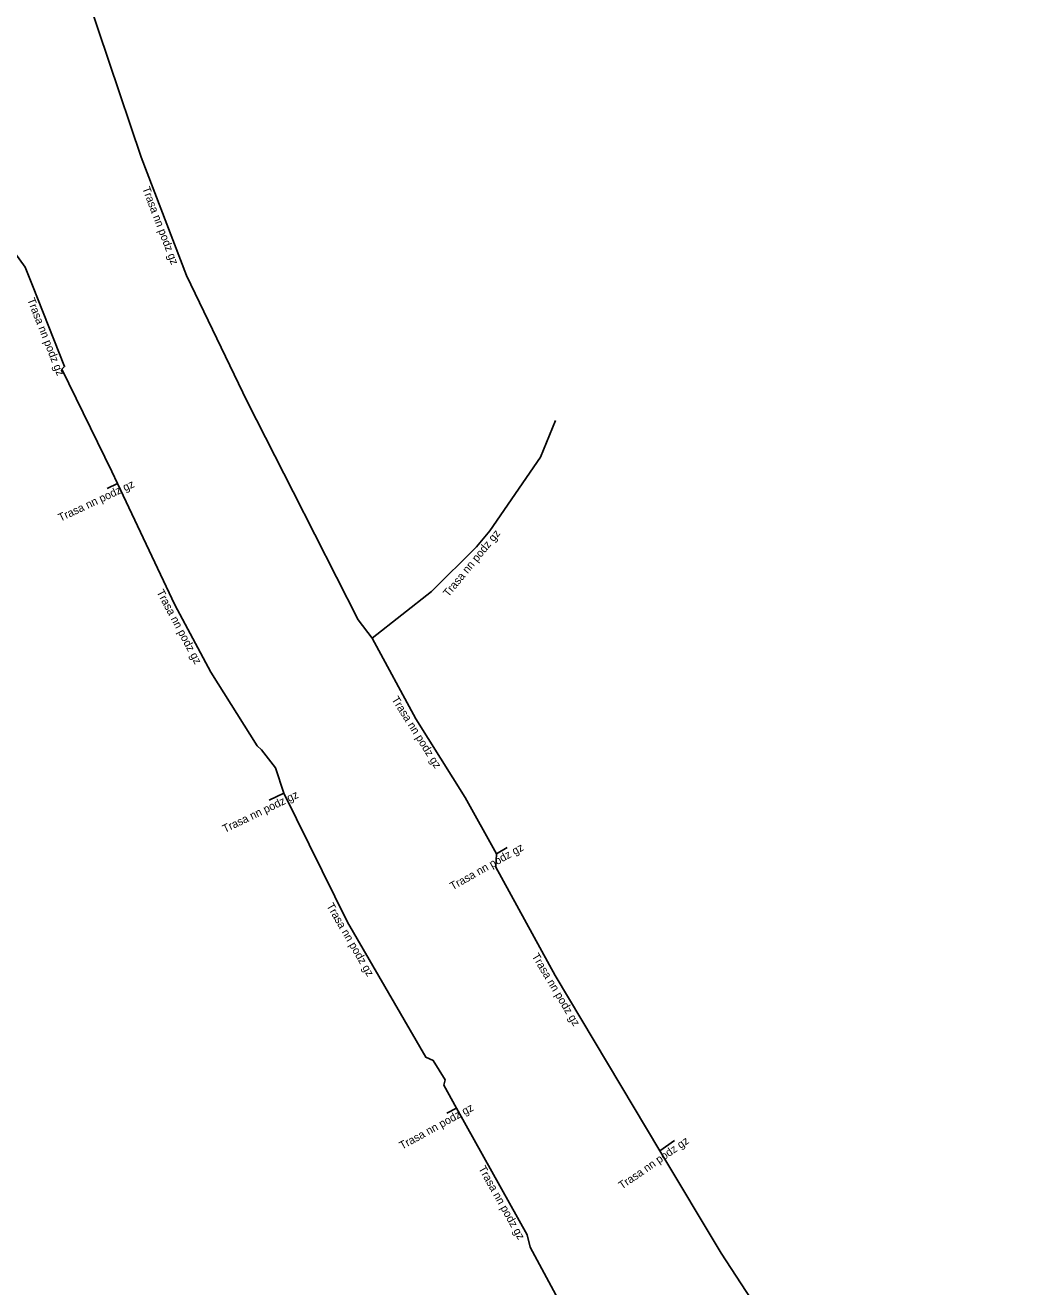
# Model space of a CAD drawing. Extents: x -660151 to -659156, y -1008082 to -1007440.
# Drawn here: x -659950.2 to -659887.3, y -1007835.1 to -1007756.3 of the extents above; entities that cross this region are included whole.
import ezdxf

# ---------------------------------------------------------------- set-up
doc = ezdxf.new("R2010")
doc.units = 0
doc.layers.add('Popiskový text - Ostatní atributy Trasy', color=7, linetype='Continuous')
doc.layers.add('Spojnice NN', color=7, linetype='Continuous')

msp = doc.modelspace()

# ---------------------------------------------------------------- linework, layer by layer
at = {"layer": 'Spojnice NN'}
for points in [[(-659928.51, -1007794.59), (-659929.38, -1007793.43), (-659933.44, -1007785.43), (-659936.32, -1007779.8), (-659940.12, -1007771.93), (-659942.94, -1007764.52), (-659946.99, -1007752.51), (-659949.6, -1007743.62)], [(-659944.43, -1007784.92), (-659944.79, -1007784.16), (-659947.9, -1007777.78), (-659947.74, -1007777.61), (-659949.74, -1007772.54), (-659950.2, -1007771.4), (-659950.85, -1007770.5), (-659951.49, -1007768.51)], [(-659928.51, -1007794.59), (-659924.79, -1007791.67), (-659921.97, -1007788.87), (-659921.15, -1007787.87), (-659917.97, -1007783.27), (-659917.05, -1007780.99)], [(-659944.43, -1007784.92), (-659945.07, -1007785.22)], [(-659934.03, -1007804.27), (-659934.55, -1007802.68), (-659935.42, -1007801.57), (-659935.69, -1007801.3), (-659938.6, -1007796.71), (-659940.84, -1007792.5), (-659944.43, -1007784.92)], [(-659920.74, -1007808.05), (-659922.69, -1007804.53), (-659925.78, -1007799.62), (-659928.51, -1007794.59)], [(-659934.03, -1007804.27), (-659934.95, -1007804.71)], [(-659923.24, -1007823.94), (-659924.03, -1007822.52), (-659923.93, -1007822.18), (-659924.68, -1007820.97), (-659925.14, -1007820.77), (-659930.04, -1007812.32), (-659934.03, -1007804.27)], [(-659920.74, -1007808.05), (-659920.07, -1007807.67)], [(-659910.52, -1007826.61), (-659917.06, -1007815.66), (-659920.78, -1007808.89), (-659920.74, -1007808.05)], [(-659923.24, -1007823.94), (-659923.84, -1007824.27)], [(-659915.85, -1007837.77), (-659918.62, -1007832.64), (-659918.81, -1007831.87), (-659923.24, -1007823.94)], [(-659910.52, -1007826.61), (-659909.6, -1007825.97)], [(-659887.32, -1007855.93), (-659889.18, -1007856.16), (-659892.04, -1007853.15), (-659897.65, -1007846.67), (-659901.71, -1007841.31), (-659903.14, -1007839), (-659902.99, -1007837.92), (-659903.87, -1007837.32), (-659906.69, -1007833.01), (-659910.52, -1007826.61)]]:
    msp.add_lwpolyline(points, dxfattribs=at)

# ---------------------------------------------------------------- texts
at = {"layer": 'Popiskový text - Ostatní atributy Trasy'}
for rotation, p in [(290.83516, (-659942.892, -1007766.474)), (291.52811, (-659950.086, -1007773.432)), (25.11483, (-659947.999, -1007787.311)), (50.64825, (-659923.734, -1007792.045)), (298.01595, (-659942.003, -1007791.699)), (302.18335, (-659927.311, -1007798.407)), (25.55997, (-659937.722, -1007806.756)), (29.56035, (-659923.472, -1007810.346)), (300.10866, (-659931.38, -1007811.305)), (300.84819, (-659918.541, -1007814.448)), (28.81079, (-659926.638, -1007826.551)), (34.82449, (-659912.886, -1007829.047)), (299.18939, (-659921.876, -1007827.714))]:
    msp.add_text('Trasa nn podz gz', height=0.5, rotation=rotation, dxfattribs=at).set_placement(p)

doc.saveas('drawing.dxf')
